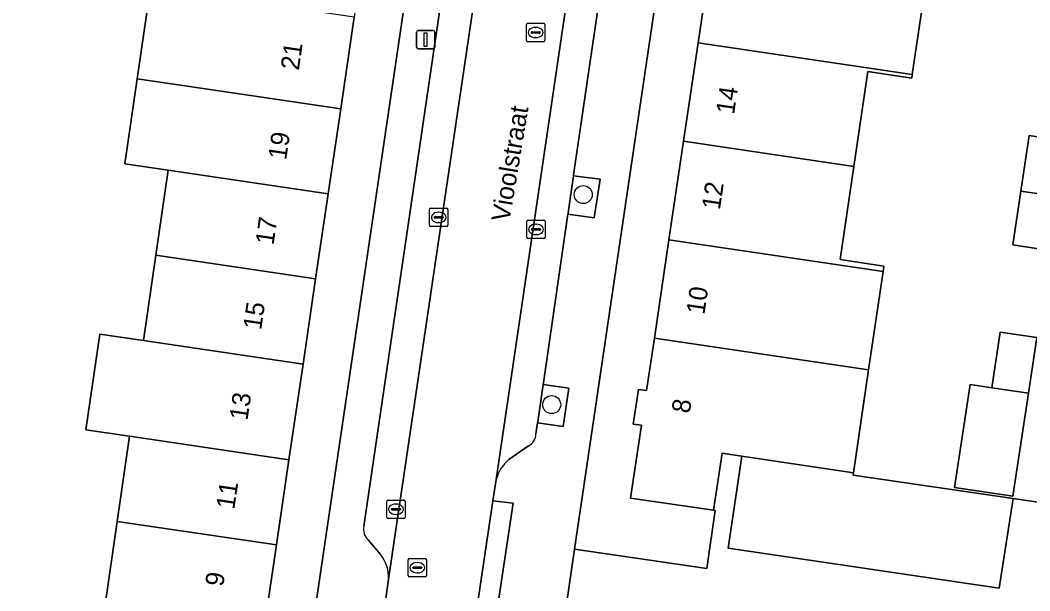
# Model space of a CAD drawing. Extents: x 164148 to 165261, y 382513 to 383432.
# Drawn here: x 164248.1 to 164302.9, y 382932 to 382962.9 of the extents above; entities that cross this region are included whole.
import ezdxf

# ---------------------------------------------------------------- set-up
doc = ezdxf.new("R2010")
doc.units = 0
for name, color, linetype in [('IMGEO_Boom', 7, 'Continuous'), ('IMGEO_Erf', 7, 'Continuous'), ('IMGEO_Groenvoorziening', 7, 'Continuous'), ('IMGEO_Kolk', 7, 'Continuous'), ('IMGEO_Lichtmast', 7, 'Continuous'), ('IMGEO_Openbare_ruimte_label', 7, 'Continuous'), ('IMGEO_Pand', 7, 'Continuous'), ('IMGEO_Pand_nummerreeks', 7, 'Continuous'), ('IMGEO_Parkeervlak_open', 7, 'Continuous'), ('IMGEO_Rijbaan_lokaal_open', 7, 'Continuous'), ('IMGEO_Rioolput', 7, 'Continuous'), ('IMGEO_Voetpad_open', 7, 'Continuous')]:
    doc.layers.add(name, color=color, linetype=linetype)

msp = doc.modelspace()

# ---------------------------------------------------------------- linework, layer by layer
at = {"layer": 'IMGEO_Boom'}
for centre in [(164278.662, 382953.445), (164276.948, 382942.055)]:
    msp.add_circle(centre, 0.489, dxfattribs=at)
at = {"layer": 'IMGEO_Erf'}
for points in [[(164291.171, 383021.984), (164278.188, 382934.213), (164285.371, 382933.164), (164285.821, 382936.306), (164285.725, 382936.32), (164281.23, 382936.985), (164281.815, 382940.929), (164281.37, 382940.995), (164281.649, 382942.874), (164282.094, 382942.808), (164282.517, 382945.656), (164283.31, 382950.998), (164284.103, 382956.338), (164284.896, 382961.68), (164285.689, 382967.022), (164286.482, 382972.362), (164287.275, 382977.705), (164287.928, 382982.106), (164288.067, 382983.046), (164288.856, 382988.388), (164289.645, 382993.73)], [(164260.833, 382908.792), (164272.503, 382987.831), (164265.514, 382988.929), (164265.229, 382987.03), (164269.688, 382986.378), (164269.099, 382982.348), (164269.632, 382982.3), (164269.326, 382980.293), (164268.792, 382980.375), (164268.428, 382977.911), (164267.576, 382972.135), (164266.907, 382967.603), (164266.238, 382963.071), (164265.504, 382958.099), (164264.822, 382953.482), (164264.141, 382948.866), (164263.459, 382944.249), (164262.692, 382939.056), (164262.011, 382934.439), (164261.328, 382929.813)], [(164252.7, 382931.09), (164253.372, 382935.717), (164254.043, 382940.336), (164251.678, 382940.679), (164252.432, 382945.875), (164254.797, 382945.531), (164255.468, 382950.15), (164256.139, 382954.767), (164253.792, 382955.114), (164254.463, 382959.727), (164255.186, 382964.7), (164257.561, 382964.355), (164258.219, 382968.889), (164258.877, 382973.423), (164256.504, 382973.779), (164257.371, 382979.553), (164259.733, 382979.198), (164260.536, 382984.54), (164249.057, 382986.385), (164248.815, 382984.183), (164250.832, 382983.893), (164250.355, 382980.586), (164249.829, 382976.93), (164247.812, 382977.22)], [(164297.296, 382965.301), (164296.508, 382959.959), (164296.479, 382959.764), (164294.105, 382960.115), (164293.346, 382954.968), (164292.6, 382949.915), (164294.975, 382949.565), (164294.932, 382949.275), (164294.144, 382943.932), (164293.322, 382938.358), (164293.303, 382938.23), (164301.982, 382936.949), (164306.127, 382936.338)]]:
    msp.add_lwpolyline(points, dxfattribs=at)
for points in [[(164302.401, 382953.626), (164302.846, 382956.647), (164304.825, 382956.347), (164304.381, 382953.333), (164303.951, 382950.417), (164301.972, 382950.716)], [(164300.83, 382942.968), (164301.287, 382945.988), (164303.266, 382945.688), (164302.809, 382942.668), (164301.965, 382937.092), (164298.804, 382937.554), (164299.65, 382943.146)]]:
    msp.add_lwpolyline(points, close=True, dxfattribs=at)
at = {"layer": 'IMGEO_Groenvoorziening'}
for points in [[(164278.131, 382954.463), (164277.838, 382952.449), (164277.833, 382952.411), (164277.83, 382952.39), (164279.252, 382952.181), (164279.573, 382954.272)], [(164276.483, 382943.137), (164276.188, 382941.111), (164276.181, 382941.063), (164277.565, 382940.859), (164277.886, 382942.95)]]:
    msp.add_lwpolyline(points, close=True, dxfattribs=at)
at = {"layer": 'IMGEO_Kolk'}
for p, q in [((164270.32, 382951.782), (164270.32, 382952.634)), ((164270.395, 382952.708), (164271.247, 382952.708)), ((164270.622, 382952.251), (164271.02, 382952.251)), ((164270.808, 382952.488), (164270.833, 382952.488)), ((164271.321, 382952.634), (164271.321, 382951.782)), ((164271.247, 382951.708), (164270.395, 382951.708)), ((164270.579, 382952.202), (164270.579, 382952.214)), ((164271.017, 382952.165), (164270.619, 382952.165)), ((164270.831, 382951.928), (164270.806, 382951.928)), ((164271.063, 382952.214), (164271.063, 382952.202)), ((164275.596, 382951.129), (164275.596, 382951.981)), ((164275.671, 382952.055), (164276.523, 382952.055)), ((164276.084, 382951.835), (164276.109, 382951.835)), ((164276.597, 382951.981), (164276.597, 382951.129)), ((164275.855, 382951.549), (164275.855, 382951.561)), ((164276.293, 382951.512), (164275.895, 382951.512)), ((164275.898, 382951.598), (164276.296, 382951.598)), ((164276.107, 382951.275), (164276.082, 382951.275)), ((164276.339, 382951.561), (164276.339, 382951.549)), ((164276.523, 382951.055), (164275.671, 382951.055)), ((164267.999, 382935.948), (164267.999, 382936.8)), ((164268.074, 382936.874), (164268.926, 382936.874)), ((164268.258, 382936.368), (164268.258, 382936.38)), ((164268.301, 382936.417), (164268.699, 382936.417)), ((164268.487, 382936.654), (164268.512, 382936.654)), ((164268.742, 382936.38), (164268.742, 382936.368)), ((164269, 382936.8), (164269, 382935.948)), ((164268.926, 382935.874), (164268.074, 382935.874)), ((164268.696, 382936.331), (164268.298, 382936.331)), ((164268.51, 382936.094), (164268.485, 382936.094))]:
    msp.add_line(p, q, dxfattribs=at)
for points in [[(164270.32, 382951.782), (164270.32, 382952.634)], [(164270.395, 382952.708), (164271.247, 382952.708)], [(164271.321, 382952.634), (164271.321, 382951.782)], [(164271.247, 382951.708), (164270.395, 382951.708)], [(164275.596, 382951.129), (164275.596, 382951.981)], [(164275.671, 382952.055), (164276.523, 382952.055)], [(164276.597, 382951.981), (164276.597, 382951.129)], [(164276.523, 382951.055), (164275.671, 382951.055)], [(164267.999, 382935.948), (164267.999, 382936.8)], [(164268.074, 382936.874), (164268.926, 382936.874)], [(164269, 382936.8), (164269, 382935.948)], [(164268.926, 382935.874), (164268.074, 382935.874)]]:
    msp.add_lwpolyline(points, dxfattribs=at)
for centre, radius, start, end in [((164270.397, 382952.632), 0.0765, 91.552, 178.448), ((164270.397, 382952.632), 0.0765, 91.552, 178.448), ((164270.619, 382952.211), 0.0403, 85.8775, 175.7526), ((164271.024, 382952.213), 0.0386, 1.7309, 96.639), ((164271.245, 382952.632), 0.0765, 1.552, 88.448), ((164271.245, 382952.632), 0.0765, 1.552, 88.448), ((164270.397, 382951.784), 0.0765, 181.552, 268.448), ((164270.397, 382951.784), 0.0765, 181.552, 268.448), ((164270.616, 382952.201), 0.0366, 178.938, 274.7102), ((164271.02, 382952.208), 0.043, 264.8664, 352.4533), ((164271.245, 382951.784), 0.0765, 271.552, 358.448), ((164271.245, 382951.784), 0.0765, 271.552, 358.448), ((164275.673, 382951.979), 0.0765, 91.552, 178.448), ((164275.673, 382951.979), 0.0765, 91.552, 178.448), ((164276.521, 382951.979), 0.0765, 1.552, 88.448), ((164276.521, 382951.979), 0.0765, 1.552, 88.448), ((164275.895, 382951.558), 0.0403, 85.8775, 175.7526), ((164275.892, 382951.548), 0.0366, 178.938, 274.7102), ((164276.296, 382951.555), 0.043, 264.8664, 352.4533), ((164276.3, 382951.56), 0.0386, 1.7309, 96.639), ((164275.673, 382951.131), 0.0765, 181.552, 268.448), ((164275.673, 382951.131), 0.0765, 181.552, 268.448), ((164276.521, 382951.131), 0.0765, 271.552, 358.448), ((164276.521, 382951.131), 0.0765, 271.552, 358.448), ((164268.076, 382936.798), 0.0765, 91.552, 178.448), ((164268.076, 382936.798), 0.0765, 91.552, 178.448), ((164268.298, 382936.377), 0.0403, 85.8775, 175.7526), ((164268.295, 382936.367), 0.0366, 178.938, 274.7102), ((164268.699, 382936.374), 0.043, 264.8664, 352.4533), ((164268.703, 382936.379), 0.0386, 1.7309, 96.639), ((164268.924, 382936.798), 0.0765, 1.552, 88.448), ((164268.924, 382936.798), 0.0765, 1.552, 88.448), ((164268.076, 382935.95), 0.0765, 181.552, 268.448), ((164268.076, 382935.95), 0.0765, 181.552, 268.448), ((164268.924, 382935.95), 0.0765, 271.552, 358.448), ((164268.924, 382935.95), 0.0765, 271.552, 358.448)]:
    msp.add_arc(centre, radius, start, end, dxfattribs=at)
for centre, major_axis, ratio, start_param, end_param in [((164270.807, 382952.208), (-0.387, 0.002), 0.722429, 4.712389, 7.853982), ((164270.832, 382952.208), (-0.39, 0.002), 0.717154, 1.570796, 4.712389), ((164276.083, 382951.555), (-0.387, 0.002), 0.722429, 4.712389, 7.853982), ((164276.108, 382951.555), (-0.39, 0.002), 0.717154, 1.570796, 4.712389), ((164268.486, 382936.374), (-0.387, 0.002), 0.722429, 4.712389, 7.853982), ((164268.511, 382936.374), (-0.39, 0.002), 0.717154, 1.570796, 4.712389)]:
    msp.add_ellipse(centre, major_axis=major_axis, ratio=ratio, start_param=start_param, end_param=end_param, dxfattribs=at)
at = {"layer": 'IMGEO_Lichtmast'}
for p, q in [((164269.611, 382961.449), (164269.611, 382962.249)), ((164269.611, 382962.249), (164269.611, 382961.449)), ((164269.711, 382962.349), (164270.501, 382962.349)), ((164270.501, 382962.349), (164269.711, 382962.349)), ((164270.601, 382962.249), (164270.601, 382961.449)), ((164270.601, 382961.449), (164270.601, 382962.249)), ((164270.501, 382961.349), (164269.711, 382961.349)), ((164269.711, 382961.349), (164270.501, 382961.349))]:
    msp.add_line(p, q, dxfattribs=at)
msp.add_lwpolyline([(164270.031, 382962.224), (164270.181, 382962.224), (164270.181, 382961.474), (164270.031, 382961.474), (164270.031, 382962.224)], dxfattribs=at)
for centre, start, end in [((164269.711, 382962.249), 90, 180), ((164269.711, 382962.249), 90, 180), ((164270.501, 382962.249), 0, 90), ((164270.501, 382962.249), 360, 90), ((164269.711, 382961.449), 180, 270), ((164269.711, 382961.449), 180, 270), ((164270.501, 382961.449), 270, 0), ((164270.501, 382961.449), 270, 0)]:
    msp.add_arc(centre, 0.1, start, end, dxfattribs=at)
at = {"layer": 'IMGEO_Pand'}
for points in [[(164297.296, 382965.301), (164285.689, 382967.022), (164284.896, 382961.68), (164296.508, 382959.959)], [(164265.504, 382958.099), (164266.238, 382963.071), (164257.561, 382964.355), (164255.186, 382964.7), (164254.463, 382959.727), (164256.81, 382959.386)], [(164296.479, 382959.764), (164296.508, 382959.959), (164284.896, 382961.68), (164284.103, 382956.338), (164293.346, 382954.968), (164294.105, 382960.115)], [(164265.504, 382958.099), (164256.81, 382959.386), (164254.463, 382959.727), (164253.792, 382955.114), (164256.139, 382954.767), (164264.822, 382953.482)], [(164304.825, 382956.347), (164302.846, 382956.647), (164302.401, 382953.626), (164304.381, 382953.333)], [(164293.346, 382954.968), (164284.103, 382956.338), (164283.31, 382950.998), (164294.932, 382949.275), (164294.975, 382949.565), (164292.6, 382949.915)], [(164255.468, 382950.15), (164264.141, 382948.866), (164264.822, 382953.482), (164256.139, 382954.767)], [(164304.381, 382953.333), (164302.401, 382953.626), (164301.972, 382950.716), (164303.951, 382950.417)], [(164294.932, 382949.275), (164283.31, 382950.998), (164282.517, 382945.656), (164294.144, 382943.932)], [(164255.468, 382950.15), (164254.797, 382945.531), (164263.459, 382944.249), (164264.141, 382948.866)], [(164262.692, 382939.056), (164263.459, 382944.249), (164254.797, 382945.531), (164252.432, 382945.875), (164251.678, 382940.679), (164254.043, 382940.336)], [(164301.287, 382945.988), (164300.83, 382942.968), (164302.809, 382942.668), (164303.266, 382945.688)], [(164294.144, 382943.932), (164282.517, 382945.656), (164282.094, 382942.808), (164281.649, 382942.874), (164281.37, 382940.995), (164281.815, 382940.929), (164281.23, 382936.985), (164285.725, 382936.32), (164286.193, 382939.41), (164287.265, 382939.252), (164293.322, 382938.358)], [(164302.809, 382942.668), (164300.83, 382942.968), (164299.65, 382943.146), (164298.804, 382937.554), (164301.965, 382937.092)], [(164262.692, 382939.056), (164254.043, 382940.336), (164253.372, 382935.717), (164262.011, 382934.439)], [(164261.328, 382929.813), (164262.011, 382934.439), (164253.372, 382935.717), (164252.7, 382931.09)]]:
    msp.add_lwpolyline(points, close=True, dxfattribs=at)
at = {"layer": 'IMGEO_Parkeervlak_open'}
for points in [[(164285.997, 383019.798), (164273.935, 382937.981)], [(164276.094, 382940.463), (164276.18, 382941.055), (164276.181, 382941.063), (164276.188, 382941.111), (164276.483, 382943.137), (164276.485, 382943.15), (164276.496, 382943.224), (164277.83, 382952.39), (164277.833, 382952.411), (164277.838, 382952.449), (164278.131, 382954.463), (164278.14, 382954.523), (164279.481, 382963.741), (164279.487, 382963.781), (164279.783, 382965.814), (164279.79, 382965.86), (164281.134, 382975.094), (164281.137, 382975.114), (164281.435, 382977.167), (164281.438, 382977.188), (164282.782, 382986.421)], [(164268.094, 382932.574), (164275.91, 382985.375)], [(164273.731, 382982.918), (164266.749, 382935.45)], [(164274.63, 382939.072), (164275.693, 382939.808)], [(164266.998, 382934.711), (164267.655, 382933.922)]]:
    msp.add_lwpolyline(points, dxfattribs=at)
msp.add_lwpolyline([(164301.982, 382936.949), (164293.303, 382938.23), (164293.322, 382938.358), (164287.265, 382939.252), (164286.516, 382934.255), (164301.235, 382932.092)], close=True, dxfattribs=at)
for centre, radius, start, end in [((164275.344, 382940.472), 0.75, 297.7186, 359.3303), ((164275.985, 382937.442), 2.12, 129.7342, 165.269), ((164267.533, 382935.303), 0.797, 169.3488, 227.8928), ((164266.185, 382932.698), 1.913, 356.295, 39.7825)]:
    msp.add_arc(centre, radius, start, end, dxfattribs=at)
at = {"layer": 'IMGEO_Rijbaan_lokaal_open'}
for points in [[(164280.514, 383016.518), (164277.25, 382994.351), (164277.211, 382994.075), (164276.079, 382986.366), (164275.91, 382985.375), (164268.094, 382932.574), (164267.789, 382930.331), (164264.507, 382908.099), (164262.402, 382894.251), (164267.326, 382893.52), (164269.536, 382908.558), (164269.642, 382909.28), (164272.102, 382925.91), (164272.225, 382926.604), (164272.552, 382928.781), (164273.761, 382936.824), (164273.935, 382937.981), (164285.997, 383019.798)], [(164306.127, 382936.338), (164301.982, 382936.949), (164301.235, 382932.092), (164286.516, 382934.255), (164287.265, 382939.252), (164286.193, 382939.41), (164285.725, 382936.32), (164285.821, 382936.306), (164285.371, 382933.164), (164278.188, 382934.213), (164277.599, 382930.234), (164284.757, 382929.176), (164284.289, 382926.042), (164284.213, 382926.053), (164283.782, 382922.964), (164284.795, 382922.813), (164285.538, 382927.658), (164300.186, 382925.513), (164299.469, 382920.718), (164301.137, 382920.472), (164301.836, 382925.251), (164316.467, 382923.089)]]:
    msp.add_lwpolyline(points, dxfattribs=at)
at = {"layer": 'IMGEO_Rioolput'}
for p, q in [((164275.578, 382961.811), (164275.578, 382962.663)), ((164275.653, 382962.737), (164276.505, 382962.737)), ((164276.579, 382962.663), (164276.579, 382961.811)), ((164275.837, 382962.231), (164275.837, 382962.243)), ((164276.275, 382962.194), (164275.877, 382962.194)), ((164275.88, 382962.28), (164276.278, 382962.28)), ((164276.066, 382962.517), (164276.091, 382962.517)), ((164276.321, 382962.243), (164276.321, 382962.231)), ((164276.505, 382961.737), (164275.653, 382961.737)), ((164276.089, 382961.957), (164276.064, 382961.957)), ((164269.158, 382932.779), (164269.158, 382933.631)), ((164269.233, 382933.705), (164270.085, 382933.705)), ((164270.159, 382933.631), (164270.159, 382932.779)), ((164269.417, 382933.199), (164269.417, 382933.211)), ((164269.855, 382933.162), (164269.457, 382933.162)), ((164269.46, 382933.248), (164269.858, 382933.248)), ((164269.646, 382933.485), (164269.671, 382933.485)), ((164269.901, 382933.211), (164269.901, 382933.199)), ((164270.085, 382932.705), (164269.233, 382932.705)), ((164269.669, 382932.925), (164269.644, 382932.925))]:
    msp.add_line(p, q, dxfattribs=at)
for points in [[(164275.578, 382961.811), (164275.578, 382962.663)], [(164275.653, 382962.737), (164276.505, 382962.737)], [(164276.579, 382962.663), (164276.579, 382961.811)], [(164276.505, 382961.737), (164275.653, 382961.737)], [(164269.158, 382932.779), (164269.158, 382933.631)], [(164269.233, 382933.705), (164270.085, 382933.705)], [(164270.159, 382933.631), (164270.159, 382932.779)], [(164270.085, 382932.705), (164269.233, 382932.705)]]:
    msp.add_lwpolyline(points, dxfattribs=at)
for centre, radius, start, end in [((164275.655, 382962.661), 0.0765, 91.552, 178.448), ((164275.655, 382962.661), 0.0765, 91.552, 178.448), ((164276.503, 382962.661), 0.0765, 1.552, 88.448), ((164276.503, 382962.661), 0.0765, 1.552, 88.448), ((164275.877, 382962.24), 0.0403, 85.8775, 175.7526), ((164275.874, 382962.23), 0.0366, 178.938, 274.7102), ((164276.278, 382962.237), 0.043, 264.8664, 352.4533), ((164276.282, 382962.242), 0.0386, 1.7309, 96.639), ((164275.655, 382961.813), 0.0765, 181.552, 268.448), ((164275.655, 382961.813), 0.0765, 181.552, 268.448), ((164276.503, 382961.813), 0.0765, 271.552, 358.448), ((164276.503, 382961.813), 0.0765, 271.552, 358.448), ((164269.235, 382933.629), 0.0765, 91.552, 178.448), ((164269.235, 382933.629), 0.0765, 91.552, 178.448), ((164270.083, 382933.629), 0.0765, 1.552, 88.448), ((164270.083, 382933.629), 0.0765, 1.552, 88.448), ((164269.457, 382933.208), 0.0403, 85.8775, 175.7526), ((164269.454, 382933.198), 0.0366, 178.938, 274.7102), ((164269.858, 382933.205), 0.043, 264.8664, 352.4533), ((164269.862, 382933.21), 0.0386, 1.7309, 96.639), ((164269.235, 382932.781), 0.0765, 181.552, 268.448), ((164269.235, 382932.781), 0.0765, 181.552, 268.448), ((164270.083, 382932.781), 0.0765, 271.552, 358.448), ((164270.083, 382932.781), 0.0765, 271.552, 358.448)]:
    msp.add_arc(centre, radius, start, end, dxfattribs=at)
for centre, major_axis, ratio, start_param, end_param in [((164276.065, 382962.237), (-0.387, 0.002), 0.722429, 4.712389, 7.853982), ((164276.09, 382962.237), (-0.39, 0.002), 0.717154, 1.570796, 4.712389), ((164269.645, 382933.205), (-0.387, 0.002), 0.722429, 4.712389, 7.853982), ((164269.67, 382933.205), (-0.39, 0.002), 0.717154, 1.570796, 4.712389)]:
    msp.add_ellipse(centre, major_axis=major_axis, ratio=ratio, start_param=start_param, end_param=end_param, dxfattribs=at)
at = {"layer": 'IMGEO_Voetpad_open'}
for points in [[(164277.599, 382930.234), (164278.188, 382934.213), (164291.171, 383021.984), (164291.752, 383025.908), (164291.869, 383026.7), (164292.499, 383030.912), (164279.108, 383032.842), (164276.628, 383033.326), (164267.895, 383034.634), (164259.465, 383035.864), (164256.481, 383036.306), (164254.721, 383036.566), (164251.734, 383037.008), (164243.28, 383038.25), (164234.568, 383039.547), (164232.031, 383039.843), (164231.418, 383035.873), (164232.471, 383035.679), (164233.544, 383035.52)], [(164232.797, 383030.552), (164231.736, 383030.737), (164230.722, 383030.829), (164230.145, 383026.845), (164232.631, 383026.437), (164241.288, 383025.142), (164249.795, 383023.891), (164252.799, 383023.446), (164254.489, 383023.195), (164257.524, 383022.745), (164263.602, 383021.819), (164274.678, 383020.194), (164277.185, 383019.869), (164273.356, 382993.681), (164272.503, 382987.831), (164260.833, 382908.792), (164261.755, 382908.618), (164261.454, 382906.808), (164260.536, 382900.643), (164259.528, 382893.877)], [(164266.749, 382935.45), (164273.731, 382982.918)], [(164279.481, 382963.741), (164278.14, 382954.523), (164278.131, 382954.463), (164279.573, 382954.272), (164279.252, 382952.181), (164277.83, 382952.39), (164276.496, 382943.224), (164276.485, 382943.15), (164276.483, 382943.137), (164277.886, 382942.95), (164277.565, 382940.859), (164276.181, 382941.063), (164276.18, 382941.055), (164276.094, 382940.463)], [(164275.693, 382939.808), (164274.63, 382939.072)], [(164273.935, 382937.981), (164273.761, 382936.824), (164274.857, 382936.708), (164273.652, 382928.66), (164272.552, 382928.781), (164272.225, 382926.604), (164272.102, 382925.91)], [(164267.655, 382933.922), (164266.998, 382934.711)], [(164267.789, 382930.331), (164268.094, 382932.574)]]:
    msp.add_lwpolyline(points, dxfattribs=at)
msp.add_lwpolyline([(164273.761, 382936.824), (164272.552, 382928.781), (164273.652, 382928.66), (164274.857, 382936.708)], close=True, dxfattribs=at)
for centre, radius, start, end in [((164275.344, 382940.472), 0.75, 297.7186, 359.3303), ((164275.985, 382937.442), 2.12, 129.7342, 165.269), ((164267.533, 382935.303), 0.797, 169.3488, 227.8928), ((164266.185, 382932.698), 1.913, 356.295, 39.7825)]:
    msp.add_arc(centre, radius, start, end, dxfattribs=at)

# ---------------------------------------------------------------- texts
at = {"layer": 'IMGEO_Openbare_ruimte_label'}
msp.add_text('Vioolstraat', height=1, rotation=80.5565, dxfattribs=at).set_placement((164274.655, 382951.928))
at = {"layer": 'IMGEO_Pand_nummerreeks'}
for s, rotation, p in [('21', 81.7247, (164263.226, 382960.152)), ('14', 81.5548, (164286.841, 382957.761)), ('19', 81.5204, (164262.539, 382955.291)), ('12', 81.5548, (164286.072, 382952.582)), ('17', 81.5879, (164261.852, 382950.677)), ('10', 81.5548, (164285.229, 382946.904)), ('15', 81.6114, (164261.184, 382946.07)), ('13', 81.5289, (164260.438, 382941.158)), ('8', 81.5548, (164284.434, 382941.542)), ('11', 81.3748, (164259.721, 382936.335)), ('9', 81.6793, (164259.124, 382932.153))]:
    msp.add_text(s, height=1, rotation=rotation, dxfattribs=at).set_placement(p)

doc.saveas('drawing.dxf')
